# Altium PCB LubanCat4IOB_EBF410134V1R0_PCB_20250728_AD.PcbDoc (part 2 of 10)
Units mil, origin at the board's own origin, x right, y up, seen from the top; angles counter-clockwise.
Board outline 5236.21 x 4055.11 mil, 6 copper layers (TOP, GND02, ART03, PWR04, GND05, BOTTOM), stack 47.2 mil thick; 614 components, 490 nets, 2311 pads, 1916 vias.
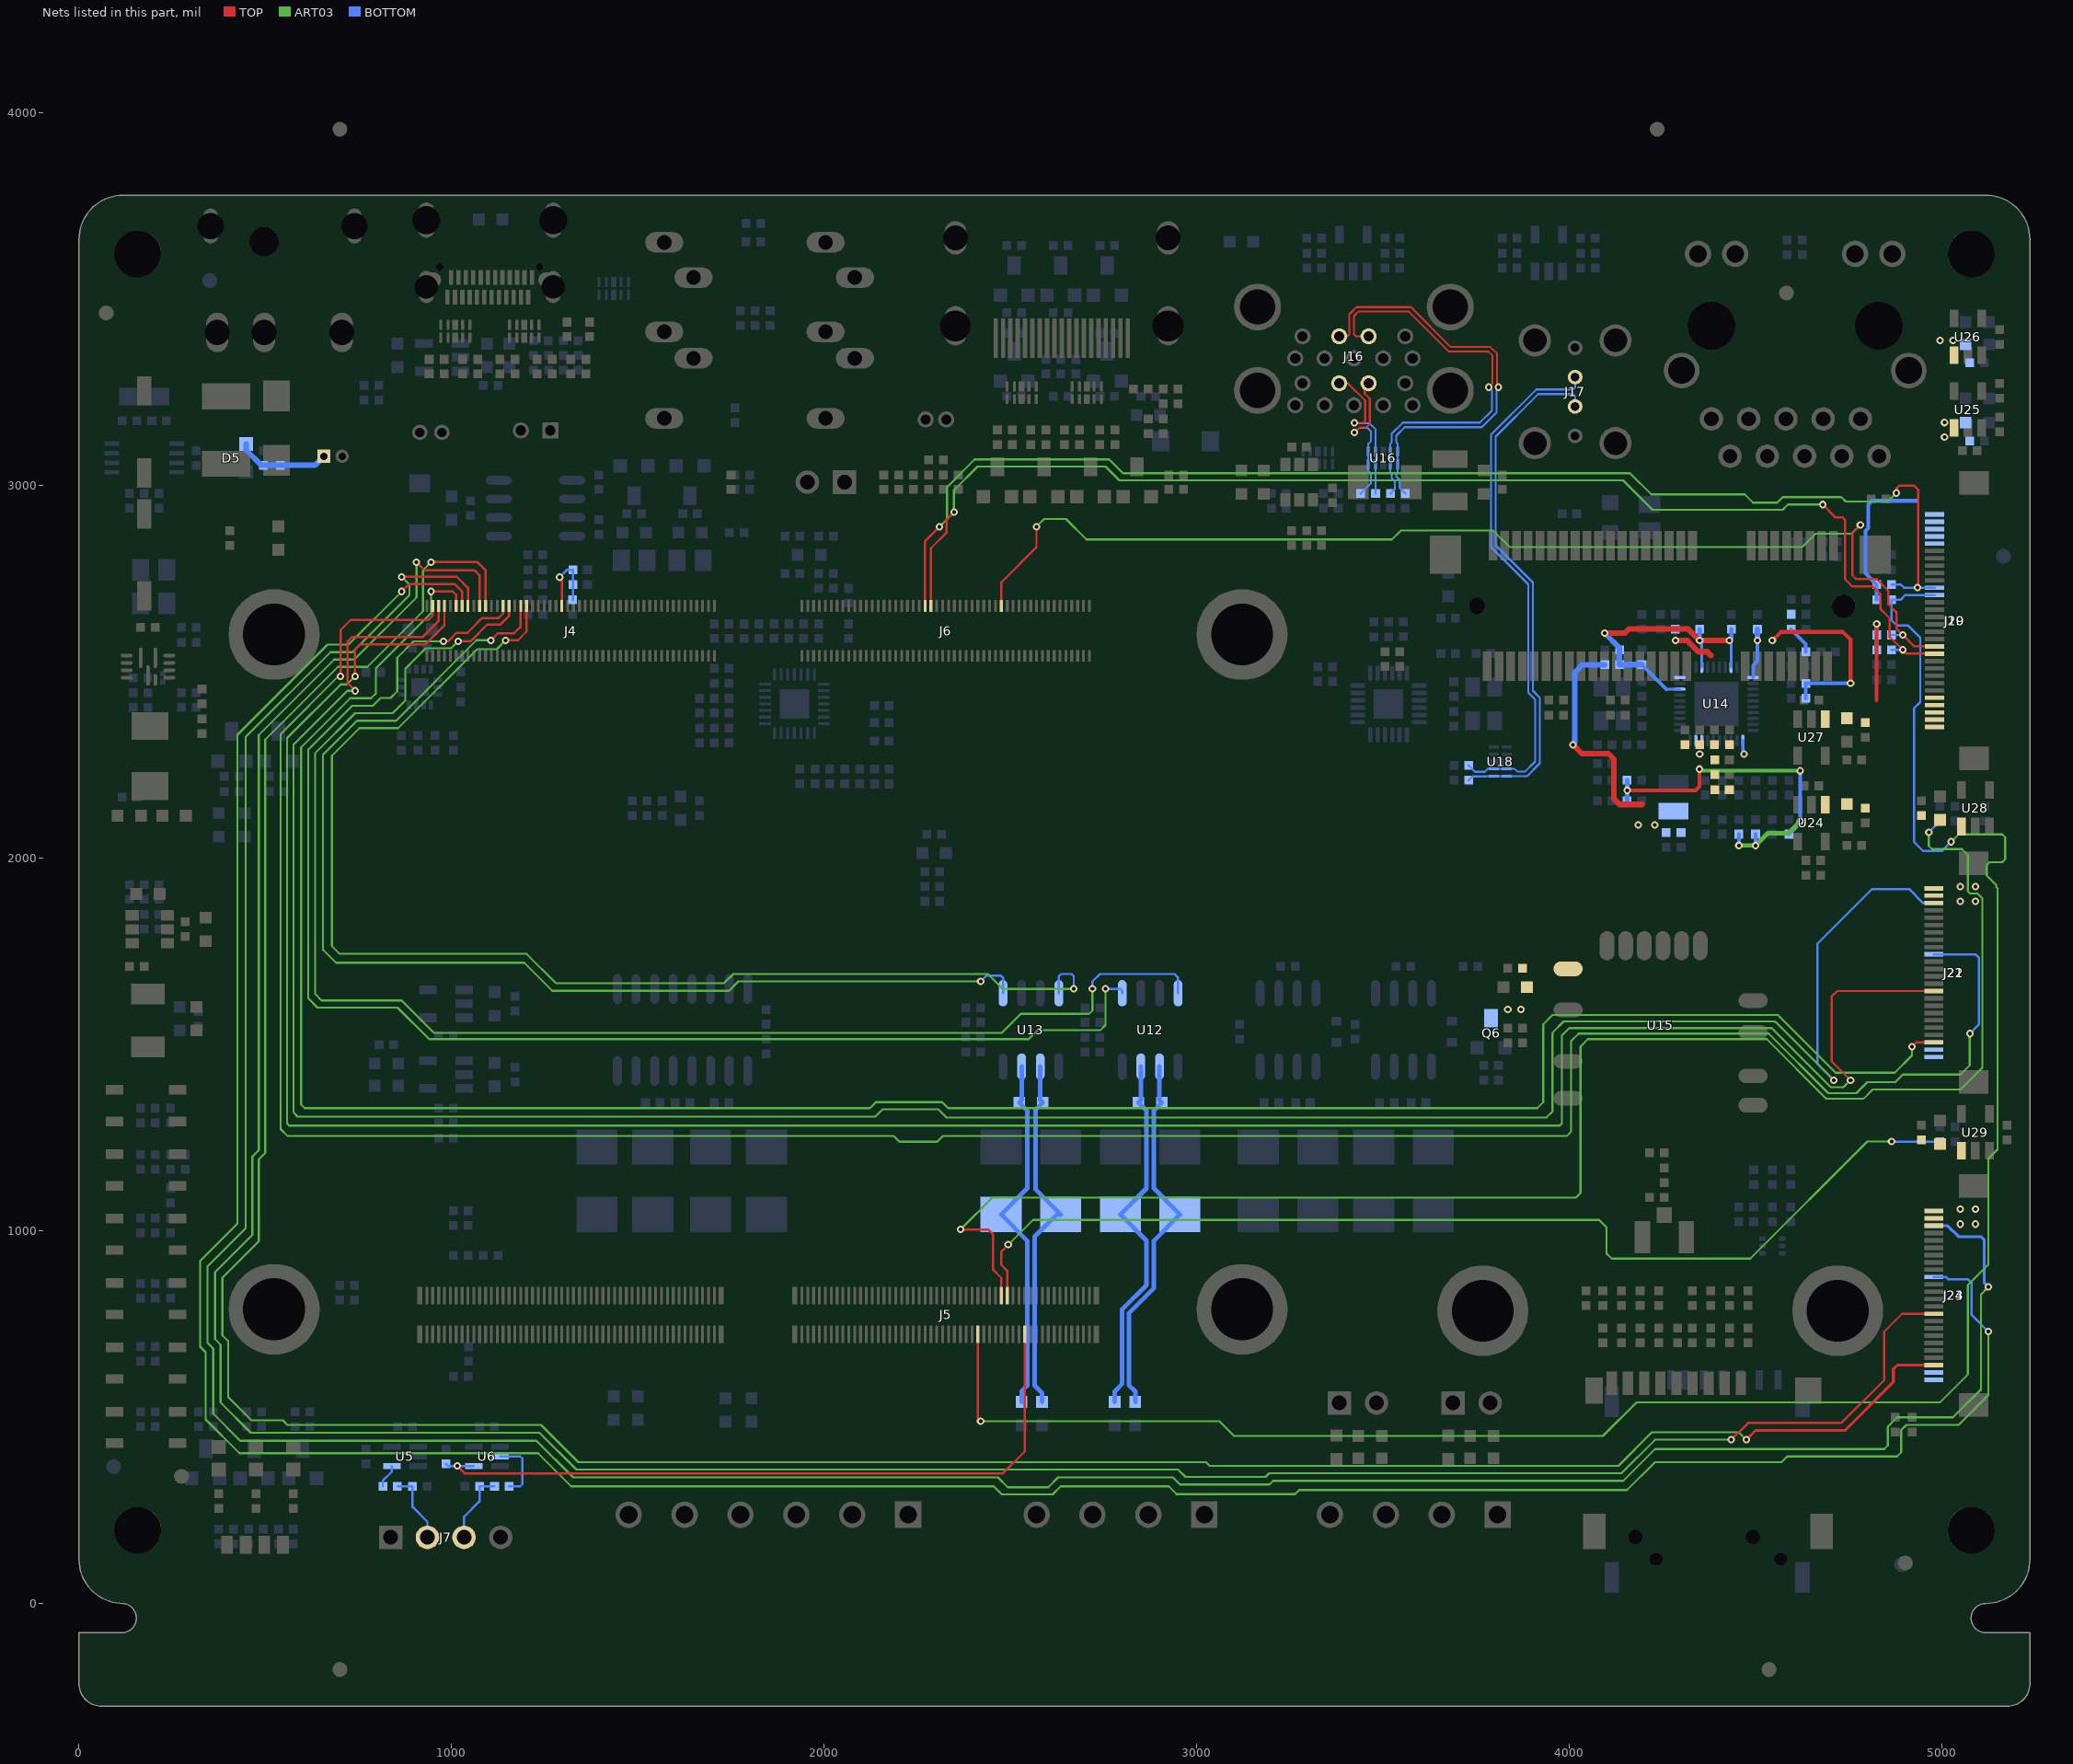
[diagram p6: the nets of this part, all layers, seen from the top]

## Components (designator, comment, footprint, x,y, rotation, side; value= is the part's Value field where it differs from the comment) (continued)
U1 "LPW5209AB5F_SOT23-5_LPW5209AB5F" SOT23-5#1 985,1419.37 r270 bottom
U2 "LPW5209AB5F_SOT23-5_LPW5209AB5F" SOT23-5#1 985,1609.37 r270 bottom
U3 "TP6327GS6_SOT23_6_ASP9135ZC-R" SOT23_6 190,1809.37 r90 top
U4 "MP8759GD-Z_QFN12-2R00X3R00_MP8759GD-Z" QFN12-2R00X3R00 185,2514.37 r270 top
U5 "74LVC1G125_SOT-353_74LVC1G125GW" SOT-353 875,394.37 r270 bottom
U6 "74LVC1G125_SOT-353_74LVC1G125GW" SOT-353 1095,394.37 r270 bottom
U7 "IRM-V838M3-C/TR1_SMD4-6R80X2R50_IRM-V838M3-C/TR1" SMD4-6R80X2R50 472.44,118.11 r180 top
U8 "HYM8563S_MSOP-8_BM8563EMA" MSOP-8 175,3074.37 r90 bottom
U9 "MAX3232CSE_SOIC16_SIT3232EESE" SOIC16 1620,1539.37 r90 bottom
U10 "SIT3088E-8P_SOP8_IC_SIT3088EESA" SOP8 3555,1539.37 r0 bottom
U11 "SIT3088E-8P_SOP8_IC_SIT3088EESA" SOP8 3245,1539.37 r0 bottom
U12 "TJA1057GT3_8P_SOP8_IC_SIT1042AQT/3" SOP8 2875,1539.37 r0 bottom
U13 "TJA1057GT3_8P_SOP8_IC_SIT1042AQT/3" SOP8 2555,1539.37 r0 bottom
U14 "RTL8211F_QFP_40P_R_RTL8211F" QFP_40P_R 4395,2414.37 r270 bottom
U15 "RTL8723_RL-UM02WBS-8723BU_TL8821CUB" RL-UM02WBS-8723BU 4245,1499.37 r180 top
U16 "RCLAMP0524P_SON10_2R50X1R00X0R50_D2550-3R3" SON10_2R50X1R00X0R50 3500,3074.37 r0 bottom
U17 "RCLAMP0524P_SON10_2R50X1R00X0R50_D2550-3R3" SON10_2R50X1R00X0R50 3325,3074.37 r0 bottom
U18 "RCLAMP0524P_SON10_2R50X1R00X0R50_D2550-3R3" SON10_2R50X1R00X0R50 3815,2259.37 r90 bottom
U19 "CH334F_QFN24_CH334F" QFN24 3515,2414.37 r0 bottom
U20 "LPW5209AB5F_SOT23-5_LPW5209AB5F" SOT23-5#2 3420,3624.37 r0 bottom
U21 "LPW5209AB5F_SOT23-5_LPW5209AB5F" SOT23-5#2 3945,3624.37 r0 bottom
U22 "RCLAMP0524P_SON10_2R50X1R00X0R50_D2550-3R3" SON10_2R50X1R00X0R50 2530,3249.37 r180 top
U23 "RCLAMP0524P_SON10_2R50X1R00X0R50_D2550-3R3" SON10_2R50X1R00X0R50 2705,3249.37 r180 top
U24 "LPW5209AB5F_SOT23-5_LPW5209AB5F" SOT23-5#1 4650,2094.37 r180 top
U25 "LPW5209AB5F_SOT23-5_LPW5209AB5F" SOT23-5#1 5070,3204.37 r0 top
U26 "LPW5209AB5F_SOT23-5_LPW5209AB5F" SOT23-5#1 5070,3399.37 r0 top
U27 "LPW5209AB5F_SOT23-5_LPW5209AB5F" SOT23-5#1 4650,2324.37 r180 top
U28 "LPW5209AB5F_SOT23-5_LPW5209AB5F" SOT23-5#1 5090,2134.37 r0 top
U29 "LPW5209AB5F_SOT23-5_LPW5209AB5F" SOT23-5#1 5090,1264.37 r0 top
U30 "TP6327GS6_SOT23_6_ASP9135ZC-R" SOT23_6 3275,3009.37 r180 top
U32 "NUP5120-D_SOT563_NUP5120X6T1G" SOT563 4545,959.37 r90 bottom
U33 "ES8388_QFN28_0R45-4X4EP2R6X2R6_ES8388" QFN28_0R45-4X4EP2R6X2R6 1920,2414.37 r0 bottom
U34 "8002A_SOP8_8002A" SOP8 1225,2939.37 r270 bottom
U35 "RCLAMP0524P_SON10_2R50X1R00X0R50_D2550-3R3" SON10_2R50X1R00X0R50 1195,3414.37 r0 top
U36 "RCLAMP0524P_SON10_2R50X1R00X0R50_D2550-3R3" SON10_2R50X1R00X0R50 1010,3414.37 r0 top
U37 "RCLAMP0524P_SON10_2R50X1R00X0R50_D2550-3R3" SON10_2R50X1R00X0R50 1435,3529.37 r0 bottom
U38 "LPW5209AB5F_SOT23-5_LPW5209AB5F" SOT23-5#1 975,3344.37 r270 bottom
U39 "FUSB302BMPX_WQFN14-0R50-2R5X2R5EP1R45X1R45_FUSB302BMPX" WQFN14-0R50-2R5X2R5EP1R45X1R45 915,2459.37 r0 bottom
Y1 "CRYSTAL_2P_3215_32.768KHZ" 3215 175,3239.37 r0 bottom
Y2 "CRYSTAL_4P_3225_IC_25MHZ" 3225 4115,2414.37 r270 bottom
Y3 "CRYSTAL_4P_3225_IC_12MHZ" 3225 3770,2414.37 r270 bottom
Z1 "DIODE BI-DIR TRIG_ES0402_KLXES15AAA1" ES0402#1 165,494.37 r90 bottom
Z2 "DIODE BI-DIR TRIG_ES0402_KLXES15AAA1" ES0402#1 165,670 r90 bottom
Z3 "DIODE BI-DIR TRIG_ES0402_KLXES15AAA1" ES0402#1 915,314.37 r0 bottom
Z4 "DIODE BI-DIR TRIG_ES0402_KLXES15AAA1" ES0402#2 1055,314.37 r0 bottom
Z5 "DIODE BI-DIR TRIG_ES0402_KLXES15AAA1" ES0402#1 165,839.37 r90 bottom
Z6 "DIODE BI-DIR TRIG_ES0402_KLXES15AAA1" ES0402#1 165,1014.37 r90 bottom
Z7 "DIODE BI-DIR TRIG_ES0402_KLXES15AAA1" ES0402#1 165,1185 r90 bottom
Z8 "DIODE BI-DIR TRIG_ES0402_KLXES15AAA1" ES0402#2 2005,2864.37 r0 bottom
Z9 "DIODE BI-DIR TRIG_ES0402_KLXES15AAA1" ES0402#1 1775,3449.37 r270 bottom
Z10 "DIODE BI-DIR TRIG_ES0402_KLXES15AAA1" ES0402#1 1760,3189.37 r90 bottom
Z11 "DIODE BI-DIR TRIG_ES0402_KLXES15AAA1" ES0402#1 1915,2864.37 r0 bottom
Z12 "DIODE BI-DIR TRIG_ES0402_KLXES15AAA1" ES0402#1 165,1310 r270 bottom

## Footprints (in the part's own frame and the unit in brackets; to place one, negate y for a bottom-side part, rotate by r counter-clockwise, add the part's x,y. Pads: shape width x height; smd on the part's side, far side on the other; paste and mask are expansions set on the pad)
3215 [mil] "3215"
  rect 55.12x47.24 smd: 1(39.4,0) 2(-39.4,0)
  silkscreen extent -75,-35 75,35, body extent -67,-24 67,24, height 150
3225 [mm] "3225"
  rect 1.3x1 smd: 1(-1.15,-0.75) 2(1.15,-0.75) 3(1.15,0.75) 4(-1.15,0.75)
  silkscreen extent -2.41,-1.52 0.3,1.2, body extent -1.9,-1.4 1.9,1.4, height 3.81
C0201 [mm] "C0201"
  rect 0.35x0.35 smd: 1(-0.275,0) 2(0.275,0)
  silkscreen extent -0.51,-0.25 0.51,0.25
C0402#1 [mil] "C0402"
  rect 23.6x23.6 smd: 1(-19.68,0) 2(19.68,0)
  silkscreen extent -37,-17 37,17, body extent -37,-17 37,17, height 150
C0402#2 [mil] "C0402"
  rect 23.6x23.6 smd: 1(19.68,0) 2(-19.68,0)
  silkscreen extent -37,-17 37,17, body extent -37,-17 37,17, height 150
C0603#1 [mil] "C0603"
  rect 31.5x31.5 smd: 1(-31.5,0) 2(31.5,0)
  silkscreen extent -55,-25 55,25, body extent -48,-16 48,16, height 150
C0603#2 [mil] "C0603"
  rect 31.5x31.5 smd: 1(31.5,0) 2(-31.5,0)
  silkscreen extent -55,-25 55,25, body extent -48,-16 48,16, height 150
C0805#1 [mm] "C0805"
  rect 1.16x1.47 smd: 1(0.89,0) 2(-0.89,0)
  silkscreen extent -1.77,-1.04 1.77,1.04, body extent -1.47,-0.74 1.47,0.74, height 3.81
C0805#2 [mm] "C0805"
  rect 1.16x1.47 smd: 1(-0.89,0) 2(0.89,0)
  silkscreen extent -1.77,-1.04 1.77,1.04, body extent -1.47,-0.74 1.47,0.74, height 3.81
CASE-B_3528 [mm] "CASE-B_3528"
  rect 1.2x2.4 smd: 1(-1.45,0) 2(1.45,0)
  silkscreen extent -2.5,-1.4 2.2,1.4, body extent -2.1,-1.2 2.1,1.2, height 3.81
CON_RA_HDMI_19P_0P5_SM [mil] "CON_RA_HDMI_19P_0P5_SM"
  rect 12x106 smd: 1(177.17,201.35) 2(157.48,201.35) 3(137.8,201.35) 4(118.11,201.35) 5(98.43,201.35) 6(78.74,201.35) 7(59.06,201.35) 8(39.37,201.35) 9(19.69,201.35) 10(0,201.35) 11(-19.69,201.35) 12(-39.37,201.35) 13(-59.06,201.35) 14(-78.74,201.35) 15(-98.43,201.35) 16(-118.11,201.35) 17(-137.8,201.35) 18(-157.48,201.35) 19(-177.17,201.35)
  oval 59x106 / inner round 60 / far side oval 59x106 hole 83 slot 35 at 0 deg: G1(285.43,167.89) G2(-285.43,167.89)
  oval 59x90 / inner round 60 / far side oval 59x90 hole 66 slot 35 at 0 deg: G3(285.43,-68.33) G4(-285.43,-68.33)
  silkscreen extent -335,-471 335,241, body extent -315,-254 315,254, height 150
DB2ERC-3P81-4P [mm] "DB2ERC-3P81-4P"
  rect 1.8x1.8 / inner round 1.524 / far side rect 1.8x1.8 hole 1.2: 1(-5.725,-3.5)
  round 1.8 / inner round 1.524 / far side round 1.8 hole 1.2: 2(-1.915,-3.5) 3(1.895,-3.5) 4(5.705,-3.5)
  silkscreen extent -9.21,-4.6 8.11,4.55, body extent -8.2,-4.7 8.2,4.7, height 3.81
DB2ERC-3P81-6P [mm] "DB2ERC-3P81-6P"
  rect 1.8x1.8 / inner round 1.524 / far side rect 1.8x1.8 hole 1.2: 1(-9.525,-3.5)
  round 1.8 hole 1.2: 2(-5.715,-3.5) 5(5.715,-3.5)
  round 1.8 / inner round 1.524 / far side round 1.8 hole 1.2: 3(-1.905,-3.5) 4(1.905,-3.5) 6(9.525,-3.5)
  silkscreen extent -12.82,-4.6 11.93,4.55, body extent -12,-4.7 12,4.7, height 3.81
DC_IN_TH_3P_10R1X11R6 [mm] "DC_IN_TH_3P_10R1X11R6"
  oval 2.4x1.001 hole 1.801 slot 0.399 at 90 deg: 1(-2.826,-4.951) 5(-2.826,4.849)
  oval 2.7x1.5 hole 1.7 slot 0.5 at 90 deg: 2(4.426,-1.301) 3(4.426,3.998)
  oval 2.7x1.5 / inner round 1.524 / far side oval 2.7x1.5 hole 1.7 slot 0.5 at 90 deg: 4(4.426,-4.501)
  round 1.999 hole 1.999 unplated: ""(-1.774,-1.301)
  silkscreen extent -5.9,-5.1 5.75,5, body extent -6.03,-5.8 6.03,5.8, height 3.81
DF40C-100DP-0P4V [mm] "DF40C-100DP-0P4V"
  rect 0.2x1.2 smd: 1(-9.8,1.325) 2(-9.8,-1.325) 3(-9.4,1.325) 4(-9.4,-1.325) 5(-9,1.325) 6(-9,-1.325) 7(-8.6,1.325) 8(-8.6,-1.325) 9(-8.2,1.325) 10(-8.2,-1.325) 11(-7.8,1.325) 12(-7.8,-1.325) 13(-7.4,1.325) 14(-7.4,-1.325) 15(-7,1.325) 16(-7,-1.325) 17(-6.6,1.325) 18(-6.6,-1.325) 19(-6.2,1.325) 20(-6.2,-1.325) 21(-5.8,1.325) 22(-5.8,-1.325) 23(-5.4,1.325) 24(-5.4,-1.325) 25(-5,1.325) 26(-5,-1.325) 27(-4.6,1.325) 28(-4.6,-1.325) 29(-4.2,1.325) 30(-4.2,-1.325) 31(-3.8,1.325) 32(-3.8,-1.325) 33(-3.4,1.325) 34(-3.4,-1.325) 35(-3,1.325) 36(-3,-1.325) 37(-2.6,1.325) 38(-2.6,-1.325) 39(-2.2,1.325) 40(-2.2,-1.325) 41(-1.8,1.325) 42(-1.8,-1.325) 43(-1.4,1.325) 44(-1.4,-1.325) 45(-1,1.325) 46(-1,-1.325) 47(-0.6,1.325) 48(-0.6,-1.325) 49(-0.2,1.325) 50(-0.2,-1.325) 51(0.2,1.325) 52(0.2,-1.325) 53(0.6,1.325) 54(0.6,-1.325) 55(1,1.325) 56(1,-1.325) 57(1.4,1.325) 58(1.4,-1.325) 59(1.8,1.325) 60(1.8,-1.325) 61(2.2,1.325) 62(2.2,-1.325) 63(2.6,1.325) 64(2.6,-1.325) 65(3,1.325) 66(3,-1.325) 67(3.4,1.325) 68(3.4,-1.325) 69(3.8,1.325) 70(3.8,-1.325) 71(4.2,1.325) 72(4.2,-1.325) 73(4.6,1.325) 74(4.6,-1.325) 75(5,1.325) 76(5,-1.325) 77(5.4,1.325) 78(5.4,-1.325) 79(5.8,1.325) 80(5.8,-1.325) 81(6.2,1.325) 82(6.2,-1.325) 83(6.6,1.325) 84(6.6,-1.325) 85(7,1.325) 86(7,-1.325) 87(7.4,1.325) 88(7.4,-1.325) 89(7.8,1.325) 90(7.8,-1.325) 91(8.2,1.325) 92(8.2,-1.325) 93(8.6,1.325) 94(8.6,-1.325) 95(9,1.325) 96(9,-1.325) 97(9.4,1.325) 98(9.4,-1.325) 99(9.8,1.325) 100(9.8,-1.325)
  rect 0.35x1.2 smd: 101(-10.275,1.325) 102(-10.275,-1.325) 103(10.275,1.325) 104(10.275,-1.325)
  silkscreen extent -10.8,-0.92 10.8,2.4, body extent -10.9,-2 10.9,2, height 3.81
DF40HC-100DS-0P4V [mm] "DF40HC-100DS-0P4V"
  rect 0.2x0.8 smd: 1(-9.8,-1.7) 2(-9.8,1.7) 3(-9.4,-1.7) 4(-9.4,1.7) 5(-9,-1.7) 6(-9,1.7) 7(-8.6,-1.7) 8(-8.6,1.7) 9(-8.2,-1.7) 10(-8.2,1.7) 11(-7.8,-1.7) 12(-7.8,1.7) 13(-7.4,-1.7) 14(-7.4,1.7) 15(-7,-1.7) 16(-7,1.7) 17(-6.6,-1.7) 18(-6.6,1.7) 19(-6.2,-1.7) 20(-6.2,1.7) 21(-5.8,-1.7) 22(-5.8,1.7) 23(-5.4,-1.7) 24(-5.4,1.7) 25(-5,-1.7) 26(-5,1.7) 27(-4.6,-1.7) 28(-4.6,1.7) 29(-4.2,-1.7) 30(-4.2,1.7) 31(-3.8,-1.7) 32(-3.8,1.7) 33(-3.4,-1.7) 34(-3.4,1.7) 35(-3,-1.7) 36(-3,1.7) 37(-2.6,-1.7) 38(-2.6,1.7) 39(-2.2,-1.7) 40(-2.2,1.7) 41(-1.8,-1.7) 42(-1.8,1.7) 43(-1.4,-1.7) 44(-1.4,1.7) 45(-1,-1.7) 46(-1,1.7) 47(-0.6,-1.7) 48(-0.6,1.7) 49(-0.2,-1.7) 50(-0.2,1.7) 51(0.2,-1.7) 52(0.2,1.7) 53(0.6,-1.7) 54(0.6,1.7) 55(1,-1.7) 56(1,1.7) 57(1.4,-1.7) 58(1.4,1.7) 59(1.8,-1.7) 60(1.8,1.7) 61(2.2,-1.7) 62(2.2,1.7) 63(2.6,-1.7) 64(2.6,1.7) 65(3,-1.7) 66(3,1.7) 67(3.4,-1.7) 68(3.4,1.7) 69(3.8,-1.7) 70(3.8,1.7) 71(4.2,-1.7) 72(4.2,1.7) 73(4.6,-1.7) 74(4.6,1.7) 75(5,-1.7) 76(5,1.7) 77(5.4,-1.7) 78(5.4,1.7) 79(5.8,-1.7) 80(5.8,1.7) 81(6.2,-1.7) 82(6.2,1.7) 83(6.6,-1.7) 84(6.6,1.7) 85(7,-1.7) 86(7,1.7) 87(7.4,-1.7) 88(7.4,1.7) 89(7.8,-1.7) 90(7.8,1.7) 91(8.2,-1.7) 92(8.2,1.7) 93(8.6,-1.7) 94(8.6,1.7) 95(9,-1.7) 96(9,1.7) 97(9.4,-1.7) 98(9.4,1.7) 99(9.8,-1.7) 100(9.8,1.7)
  silkscreen extent -11.3,-2.55 11.3,1.5, body extent -11.4,-2.2 11.4,2.2, height 3.81
EAR_JACK [mm] "EAR_JACK"
  oval 1.4x2.6 / inner round 1.524 / far side oval 1.4x2.6 hole 1 slot 2 at 90 deg: 1(-5.904,-0.05) 2(-3.504,1.95) 3(1.996,1.95) 4(6.096,-0.05) 5(0.196,-0.05)
  silkscreen extent -11.12,-4.06 7.2,4.06, body extent -7.2,-4.15 7.2,4.15, height 3.81
EC6P3 [mil] "EC6P3"
  rect 39.4x78.7 smd: 1(0,110.24) 2(0,-110.24)
  silkscreen extent -130,-130 130,130, body extent -138,-157 138,157, height 150
ES0402#1 [mil] "ES0402"
  rect 23.6x23.6 smd: 1(-19.68,0) 2(19.68,0)
  silkscreen extent -37,-17 37,17, body extent -37,-17 37,17, height 150
ES0402#2 [mil] "ES0402"
  rect 23.6x23.6 smd: 1(19.68,0) 2(-19.68,0)
  silkscreen extent -37,-17 37,17, body extent -37,-17 37,17, height 150
F1812 [mm] "F1812"
  rect 1.78x3.3 smd: 1(-2.305,0) 2(2.305,0)
  silkscreen extent -3.4,-1.9 3.4,1.9, body extent -3.4,-1.9 3.4,1.9, height 3.81
FPC-30P-0P5 [mm] "FPC-30P-0P5"
  rect 0.3x1.3 smd: 1(-7.25,2.733) 2(-6.75,2.733) 3(-6.25,2.733) 4(-5.75,2.733) 5(-5.25,2.733) 6(-4.75,2.733) 7(-4.25,2.733) 8(-3.75,2.733) 9(-3.25,2.733) 10(-2.75,2.733) 11(-2.25,2.733) 12(-1.75,2.733) 13(-1.25,2.733) 14(-0.75,2.733) 15(-0.25,2.733) 16(0.25,2.733) 17(0.75,2.733) 18(1.25,2.733) 19(1.75,2.733) 20(2.25,2.733) 21(2.75,2.733) 22(3.25,2.733) 23(3.75,2.733) 24(4.25,2.733) 25(4.75,2.733) 26(5.25,2.733) 27(5.75,2.733) 28(6.25,2.733) 29(6.75,2.733) 30(7.25,2.733)
  rect 1.6x2 smd: 31(9.4,0.032) 32(-9.4,0.032)
  silkscreen extent -10.05,-3.27 10.05,4.14, body extent -10.05,-3.35 10.05,3.35, height 3.81
FPC_24P_0P5 [mm] "FPC_24P_0P5"
  rect 0.3x1.3 smd: 1(-5.75,-2.701) 2(-5.25,-2.701) 3(-4.75,-2.701) 4(-4.25,-2.701) 5(-3.75,-2.701) 6(-3.25,-2.701) 7(-2.75,-2.701) 8(-2.25,-2.701) 9(-1.75,-2.701) 10(-1.25,-2.701) 11(-0.75,-2.701) 12(-0.25,-2.701) 13(0.25,-2.701) 14(0.75,-2.701) 15(1.25,-2.701) 16(1.75,-2.701) 17(2.25,-2.701) 18(2.75,-2.701) 19(3.25,-2.701) 20(3.75,-2.701) 21(4.25,-2.701) 22(4.75,-2.701) 23(5.25,-2.701) 24(5.75,-2.701)
  rect 1.6x2 smd: 25(7.45,0.001) 26(-7.45,0.001)
  silkscreen extent -8.1,-3.95 8.1,3.35
GH1P25_TH_2P [mm] "GH1P25_TH_2P"
  rect 0.9x0.9 / inner round 1.524 / far side rect 0.9x0.9 hole 0.5: 1(-0.626,-0.849)
  round 0.9 hole 0.5: 2(0.624,-0.849)
  silkscreen extent -2.2,-1.75 2.2,1.75
HDR1X2-2R54-TM-VM [mm] "HDR1X2-2R54-TM-VM"
  rect 1.6x1.6 / inner round 1.524 / far side rect 1.6x1.6 hole 1: 1(-1.27,0)
  round 1.6 / inner round 1.524 / far side round 1.6 hole 1: 2(1.27,0)
  silkscreen extent -2.54,-1.25 2.54,1.25, body extent -2.54,-1.25 2.54,1.25, height 3.81
HY911130A [mm] "HY911130A"
  round 1.6 / inner round 1.524 / far side round 1.6 hole 1: 1(5.72,-8.79) 2(4.45,-6.25) 3(3.18,-8.79) 4(1.91,-6.25) 5(0.64,-8.79) 6(-0.63,-6.25) 7(-1.9,-8.79) 8(-3.17,-6.25) 9(-4.44,-8.79)
  round 1.6 hole 1: 10(-5.71,-6.25)
  round 1.8 / inner round 1.524 / far side round 1.8 hole 1.2: 11(6.625,5) 12(4.085,5) 13(-4.085,5) 14(-6.625,5)
  round 2.43 / inner round 1.524 / far side round 2.43 hole 1.83: 15(7.745,-2.95) 16(-7.745,-2.95)
  round 3.25 hole 3.25 unplated: ""(-5.715,0.1) ""(5.715,0.1)
  silkscreen extent -8.02,-10.3 8.02,17.1, body extent -9.2,-11.1 9.2,11.1, height 3.81
L0518 [mm] "L0518"
  rect 1.9x2.5 smd: 1(-2.05,0) 2(2.05,0)
  silkscreen extent -2.75,-2.65 2.75,2.65, body extent -3.1,-2.8 3.1,2.8, height 3.81
L0603#1 [mil] "L0603"
  rect 31.5x31.5 smd: 1(-31.5,0) 2(31.5,0)
  silkscreen extent -54,-24 55,24, body extent -47,-16 47,16, height 150
L0603#2 [mil] "L0603"
  rect 31.5x31.5 smd: 1(31.5,0) 2(-31.5,0)
  silkscreen extent -55,-24 54,24, body extent -47,-16 47,16, height 150
L2520 [mil] "L2520"
  rect 44x80 smd: 1(-37.75,0) 2(37.75,0)
  silkscreen extent -68,-48 68,48, body extent -65,-45 65,45, height 150
L4520 [mil] "L4520"
  rect 55.12x90.55 smd: 1(-70.97,-0.1) 2(70.77,-0.1)
  silkscreen extent -91,-87 90,87, body extent -91,-87 91,87, height 150
LED0603 [mil] "LED0603"
  rect 36.61x38.58 smd: 1(30.32,0) 2(-30.31,0)
  silkscreen extent -60,-31 80,31, body extent -49,-19 49,19, height 150
MIC2-4R00-TM [mm] "MIC2-4R00-TM"
  round 1.1 / inner round 1.524 / far side round 1.1 hole 0.7: 1(-0.7,-0.55) 2(0.7,-0.55)
  silkscreen extent -2,-2 2,2, body extent -2.11,-2.11 2.11,2.11, height 3.81
MSOP-8 [mm] "MSOP-8"
  rect 0.3x1 smd: 1(-0.975,-2.2) 2(-0.325,-2.2) 3(0.325,-2.2) 4(0.975,-2.2) 5(0.975,2.2) 6(0.325,2.2) 7(-0.325,2.2) 8(-0.975,2.2)
  silkscreen extent -1.5,-3.3 1.5,1.5, body extent -1.5,-2.8 1.5,2.8, height 3.81
NANO_SIM [mm] "NANO_SIM"
  rect 0.5x1.3 smd: 1(-0.25,-6.94) 2(2.29,-6.94) 3(4.83,-6.94) 4(-2.47,-6.94) 5(-1.52,-6.94) 6(1.02,-6.94) 7(3.56,-6.94)
  rect 1x2.1 smd: 8(6.5,-5.46) 9(-6.5,-5.46) 10(6.5,6.54) 11(-6.5,6.54)
  round 0.9 hole 0.9 unplated: ""(-3.5,5.29) ""(5,5.29)
  silkscreen extent -6.14,-5.9 6.14,7.6, body extent -7.05,-7.64 7.05,7.64, height 3.81
NPTH_M3 [mm] "NPTH_M3"
  round 3.2 / inner round 1.524 / far side round 3.2 hole 3.2 unplated: 1(0,0)
  body extent -3.11,-3.11 3.11,3.11, height 3.81
PCIE_52P [mm] "PCIE_52P"
  rect 0.6x2 smd: 1(-11.8,-4.1) 2(-11.4,4.1) 3(-11,-4.1) 4(-10.6,4.1) 5(-10.2,-4.1) 6(-9.8,4.1) 7(-9.4,-4.1) 8(-9,4.1) 9(-8.6,-4.1) 10(-8.2,4.1) 11(-7.8,-4.1) 12(-7.4,4.1) 13(-7,-4.1) 14(-6.6,4.1) 15(-6.2,-4.1) 16(-5.8,4.1) 17(-2.2,-4.1) 18(-1.8,4.1) 19(-1.4,-4.1) 20(-1,4.1) 21(-0.6,-4.1) 22(-0.2,4.1) 23(0.2,-4.1) 24(0.6,4.1) 25(1,-4.1) 26(1.4,4.1) 27(1.8,-4.1) 28(2.2,4.1) 29(2.6,-4.1) 30(3,4.1) 31(3.4,-4.1) 32(3.8,4.1) 33(4.2,-4.1) 34(4.6,4.1) 35(5,-4.1) 36(5.4,4.1) 37(5.8,-4.1) 38(6.2,4.1) 39(6.6,-4.1) 40(7,4.1) 41(7.4,-4.1) 42(7.8,4.1) 43(8.2,-4.1) 44(8.6,4.1) 45(9,-4.1) 46(9.4,4.1) 47(9.8,-4.1) 48(10.2,4.1) 49(10.6,-4.1) 50(11,4.1) 51(11.4,-4.1) 52(11.8,4.1)
  rect 2.15x2.6 smd: 53(14.65,-3.5) 54(-14.65,-3.5)
  round 1.6 hole 1.6 unplated: ""(-12.5,0)
  round 1.1 hole 1.1 unplated: ""(12.5,0)
  silkscreen extent -15,-4.6 15,50.95, body extent -15.8,-5.2 15.8,5.2, height 3.81
PH-1X2-2P0_L [mm] "PH-1X2-2P0_L"
  rect 1.1x1.1 / inner round 1.524 / far side rect 1.1x1.1 hole 0.7: 1(-1,-0.6)
  round 1.1 / inner round 1.524 / far side round 1.1 hole 0.7: 2(1,-0.6)
  silkscreen extent -3,-2.6 3,2.6, body extent -3.1,-2.7 3.1,2.7, height 3.81
QFN12-2R00X3R00 [mm] "QFN12-2R00X3R00"
  oval 1.4x0.25 smd: 1(-0.6,0.5) 2(-0.6,-0.5) 7(0.6,0)
  oval 0.25x0.8 smd: 3(-0.75,-1.45) 4(-0.25,-1.45) 5(0.25,-1.45) 6(0.75,-1.45) 9(0.75,1.45) 10(0.25,1.45) 11(-0.25,1.45) 12(-0.75,1.45)
  oval 0.8x0.25 smd: 8(0.9,0.5)
  silkscreen extent -2.29,-2 1.5,2, body extent -1.5,-2 1.5,2, height 3.81
QFN24 [mm] "QFN24"
  rect 1x0.3 smd: 1(2.1,-1.25) 2(2.1,-0.75) 3(2.1,-0.25) 4(2.1,0.25) 5(2.1,0.75) 6(2.1,1.25) 13(-2.1,1.25) 14(-2.1,0.75) 15(-2.1,0.25) 16(-2.1,-0.25) 17(-2.1,-0.75) 18(-2.1,-1.25)
  rect 0.3x1 smd: 7(1.25,2.1) 8(0.75,2.1) 9(0.25,2.1) 10(-0.25,2.1) 11(-0.75,2.1) 12(-1.25,2.1) 19(-1.25,-2.1) 20(-0.75,-2.1) 21(-0.25,-2.1) 22(0.25,-2.1) 23(0.75,-2.1) 24(1.25,-2.1)
  rect 2x2 smd: 25(0,0)
  silkscreen extent -2.1,-2.29 2.79,2.1, body extent -2.7,-2.7 2.7,2.7, height 3.81
QFN28_0R45-4X4EP2R6X2R6 [mm] "QFN28_0R45-4X4EP2R6X2R6"
  oval 0.8x0.2 smd: 1(2,-1.35)
  rect 0.8x0.2 smd: 2(2,-0.9) 3(2,-0.45) 4(2,0) 5(2,0.45) 6(2,0.9) 7(2,1.35) 15(-2,1.35) 16(-2,0.9) 17(-2,0.45) 18(-2,0) 19(-2,-0.45) 20(-2,-0.9) 21(-2,-1.35)
  rect 0.2x0.8 smd: 8(1.35,2) 9(0.9,2) 10(0.45,2) 11(0,2) 12(-0.45,2) 13(-0.9,2) 14(-1.35,2) 22(-1.35,-2) 23(-0.9,-2) 24(-0.45,-2) 25(0,-2) 26(0.45,-2) 27(0.9,-2) 28(1.35,-2)
  rect 2x2 smd: 29(0,0)
  silkscreen extent -2,-2.03 3.15,2, body extent -2.5,-2.5 2.5,2.5, height 3.81
QFP_40P_R [mil] "QFP_40P_R"
  oval 31.5x8.66 smd: 1(-98.43,70.87) 2(-98.43,55.12) 3(-98.43,39.37) 4(-98.43,23.62) 5(-98.43,7.87) 6(-98.43,-7.87) 7(-98.43,-23.62) 8(-98.43,-39.37) 9(-98.43,-55.12) 10(-98.43,-70.87) 21(98.43,-70.87) 22(98.43,-55.12) 23(98.43,-39.37) 24(98.43,-23.62) 25(98.43,-7.87) 26(98.43,7.87) 27(98.43,23.62) 28(98.43,39.37) 29(98.43,55.12) 30(98.43,70.87)
  oval 8.66x31.5 smd: 11(-70.87,-98.43) 12(-55.12,-98.43) 13(-39.37,-98.43) 14(-23.62,-98.43) 15(-7.87,-98.43) 16(7.87,-98.43) 17(23.62,-98.43) 18(39.37,-98.43) 19(55.12,-98.43) 20(70.87,-98.43) 31(70.87,98.43) 32(55.12,98.43) 33(39.37,98.43) 34(23.62,98.43) 35(7.87,98.43) 36(-7.87,98.43) 37(-23.62,98.43) 38(-39.37,98.43) 39(-55.12,98.43) 40(-70.87,98.43)
  rect 118.11x118.11 smd: 41(0,0)
  silkscreen extent -124,-98 98,124, body extent -116,-116 116,116, height 150
R0402#1 [mil] "R0402"
  rect 23.6x23.6 smd: 1(19.68,0) 2(-19.68,0)
  silkscreen extent -37,-17 37,17, body extent -37,-17 37,17, height 150
R0402#2 [mil] "R0402"
  rect 23.6x23.6 smd: 1(-19.68,0) 2(19.68,0)
  silkscreen extent -37,-17 37,17, body extent -37,-17 37,17, height 150
R0603#1 [mil] "R0603"
  rect 31.5x31.5 smd: 1(-31.5,0) 2(31.5,0)
  silkscreen extent -54,-24 55,24, body extent -47,-16 47,16, height 150
R0603#2 [mil] "R0603"
  rect 31.5x31.5 smd: 1(31.5,0) 2(-31.5,0)
  silkscreen extent -55,-24 54,24, body extent -47,-16 47,16, height 150
R0805 [mil] "R0805"
  rect 40x45 smd: 1(-40,0) 2(40,0)
  silkscreen extent -70,-35 70,35, body extent -60,-25 60,25, height 150
RL-UM02WBS-8723BU [mm] "RL-UM02WBS-8723BU"
  oval 2x1 smd: 1(-6.3,4.122) 2(-6.3,2.122) 3(-6.3,-0.858) 4(-6.3,-3.018) 5(6.3,3.652) 6(6.3,1.122) 7(6.3,-2.378) 8(6.3,-5.178)
  oval 1x2 smd: 9(3.65,-6.748) 10(2.38,-6.748) 11(1.11,-6.748) 12(-0.16,-6.748) 13(-1.43,-6.748) 14(-2.7,-6.748)
  silkscreen extent -6.1,-6.55 6.1,6.45, body extent -6.1,-6.45 6.1,6.45, height 3.81
SMA_CA [mm] "SMA_CA"
  rect 2.1x1.8 smd: 1(-2.2,0) 2(2.2,0)
  silkscreen extent -2.2,-1.3 2.2,1.3, body extent -3.3,-1.4 3.3,1.4, height 3.81
SMB-CA [mm] "SMB-CA"
  rect 2.4x2.8 smd: 1(-2.3,0) 2(2.3,0)
  silkscreen extent -2.3,-1.8 2.3,1.8, body extent -3.5,-1.8 3.5,1.8, height 3.81
SMD4-6R80X2R50 [mm] "SMD4-6R80X2R50"
  rect 0.8x1.2 smd: 1(1.905,-1) 2(0.635,-1) 3(-0.635,-1) 4(-1.905,-1)
  silkscreen extent -3.4,-2.45 3.4,1.71, body extent -3.6,-1.8 3.6,1.8, height 3.81
SMTSO-M2R5 [mm] "SMTSO-M2R5"
  round 6.2 / inner round 5.2 / far side round 5.2 hole 4.22: 1(0,0)
  body extent -3.21,-3.21 3.21,3.21, height 3.81
SOD523 [mm] "SOD523"
  rect 0.6x0.7 smd: 1(-0.71,0) 2(0.71,0)
  silkscreen extent -1.3,-0.5 0.6,0.5, body extent -1.1,-0.4 1.1,0.4, height 3.81
SOD-123#1 [mm] "SOD-123"
  rect 1.2x1.4 smd: 1(1.7,0) 2(-1.7,0)
  silkscreen extent -1.8,-0.9 1.8,0.9, body extent -2.4,-1 2.4,1, height 3.81
SOD-123#2 [mm] "SOD-123"
  rect 1.2x1.4 smd: 1(-1.7,0) 2(1.7,0)
  silkscreen extent -1.8,-0.9 1.8,0.9, body extent -2.4,-1 2.4,1, height 3.81
SOIC16 [mil] "SOIC16"
  oval 80x24 smd: 1(-109.8,174.8) 2(-109.8,125.2) 3(-109.8,74.8) 4(-109.8,25.2) 5(-109.8,-25.2) 6(-109.8,-74.8) 7(-109.8,-125.2) 8(-109.8,-174.8) 9(109.8,-174.8) 10(109.8,-125.2) 11(109.8,-74.8) 12(109.8,-25.2) 13(109.8,25.2) 14(109.8,74.8) 15(109.8,125.2) 16(109.8,174.8)
  silkscreen extent -135,-197 59,225, body extent -157,-205 157,205, height 150
SON10_2R50X1R00X0R50 [mm] "SON10_2R50X1R00X0R50"
  rect 0.2x0.68 smd: 1(-1,-0.437) 2(-0.5,-0.437) 4(0.5,-0.437) 5(1,-0.437) 6(1,0.437) 7(0.5,0.437) 9(-0.5,0.437) 10(-1,0.437)
  rect 0.4x0.68 smd: 3(0,-0.437) 8(0,0.437)
  silkscreen extent -2.05,-0.98 1.25,0.5, body extent -1.39,-0.64 1.39,0.64, height 3.81
SOP8 [mm] "SOP8"
  oval 0.6x1.8 smd: 1(-1.905,-2.5) 2(-0.635,-2.5) 3(0.635,-2.5) 4(1.905,-2.5) 5(1.905,2.5) 6(0.635,2.5) 7(-0.635,2.5) 8(-1.905,2.5)
  silkscreen extent -2.5,-4.15 2.5,1.4, body extent -2.5,-3.5 2.5,3.5, height 3.81
SOT23#1 [mil] "SOT23"
  rect 36x36 smd: 1(-37.5,-43.5) 2(37.5,-43.5)
  rect 36x50 smd: 3(0,36.5)
  silkscreen extent -55,-54 55,36, body extent -56,-62 56,62, height 150
SOT23#2 [mil] "SOT23"
  rect 36x36 smd: 1(37.5,43.5) 2(-37.5,43.5)
  rect 36x50 smd: 3(0,-36.5)
  silkscreen extent -55,-36 55,54, body extent -56,-62 56,62, height 150
SOT23-5#1 [mm] "SOT23-5"
  rect 0.599x1.199 smd: 1(-0.95,-1.25) 2(0,-1.25) 3(0.95,-1.25) 4(0.95,1.25) 5(-0.95,1.25)
  silkscreen extent -2.02,-1.92 1.5,0.9, body extent -1.6,-1.9 1.6,1.9, height 3.81
SOT23-5#2 [mm] "SOT23-5"
  rect 0.599x1.199 smd: 1(0.95,1.25) 2(0,1.25) 3(-0.95,1.25) 4(-0.95,-1.25) 5(0.95,-1.25)
  silkscreen extent -1.5,-0.9 1.5,2.55, body extent -1.6,-1.9 1.6,1.9, height 3.81
SOT23_6 [mm] "SOT23_6"
  rect 0.7x0.9 smd: 1(-0.95,-1.2) 2(0,-1.2) 3(0.95,-1.2) 4(0.95,1.2) 5(0,1.2) 6(-0.95,1.2)
  silkscreen extent -2.19,-1.25 1.4,0.6, body extent -1.4,-1.2 1.4,1.2, height 3.81
SOT563 [mm] "SOT563"
  rect 0.3x0.45 smd: 1(-0.5,-0.675) 2(0,-0.675) 3(0.5,-0.675) 4(0.5,0.675) 5(0,0.675) 6(-0.5,0.675)
  silkscreen extent -0.9,-1.8 0.9,1.1, body extent -0.9,-1.1 0.9,1.1, height 3.81
SOT-353 [mil] "SOT-353"
  rect 16x47 smd: 1(-25.91,-35.43) 2(-0.32,-35.43) 3(25.28,-35.43) 4(25.28,35.43) 5(-25.91,35.43)
  silkscreen extent -55,-80 45,70, body extent -40,-65 40,65, height 150
SW4-4R20X3R25-SM [mm] "SW4-4R20X3R25-SM"
  rect 1.2x0.65 smd: 1(-2.15,1.075) 2(2.15,1.075) 3(2.15,-1.075) 4(-2.15,-1.075)
  silkscreen extent -2.1,-1.6 2.1,1.6, body extent -2.8,-1.7 2.8,1.7, height 3.81
TFCARD [mm] "TFCARD"
  rect 0.7x1.6 smd: 1(2.25,6.85) 2(1.15,6.85) 3(0.05,6.85) 4(-1.05,6.85) 5(-2.15,6.85) 6(-3.25,6.85) 7(-4.35,6.85) 8(-5.45,6.85) 9(-6.55,6.85)
  rect 1.2x1.778 smd: 10(-7.75,6.35)
  rect 1.524x2.413 smd: 11(-7.75,-3.25) 12(7.75,-3.25)
  rect 1.778x1.778 smd: 13(6.85,6.35)
  round 1 hole 1 unplated: ""(-4.95,-3.65) ""(3.05,-3.65)
  silkscreen extent -7.45,-12.85 7.45,6.85, body extent -8.51,-7.65 8.51,7.65, height 3.81
UFL-3 [mil] "UFL-3"
  rect 41.34x41.34 smd: 1(0,-40.85)
  rect 41.34x86.61 smd: 2(-59.06,18.21) 3(59.06,18.21)
  body extent -80,-62 80,62, height 150
USB3D0-AF-18P [mm] "USB3D0-AF-18P"
  round 1.1 / inner round 1.524 / far side round 1.1 hole 0.7: 1(-3.5,2.899) 2(-1.001,2.899) 3(1.001,2.899) 5(4,4.401) 6(1.999,4.401) 8(-1.999,4.401) 9(-4.001,4.401) 10(-3.5,6.1) 11(-1.001,6.1) 12(1.001,6.1) 14(4,7.601) 15(1.999,7.601) 17(-1.999,7.601) 18(-4.001,7.601)
  round 1.1 hole 0.7: 4(3.5,2.899) 7(0,4.401) 13(3.5,6.1) 16(0,7.601)
  round 3.2 hole 2.4: 19(6.571,0.9) 20(6.571,6.58) 21(-6.571,6.58) 22(-6.571,0.9)
  silkscreen extent -8,-16.73 8,8.77, body extent -8.4,-8.8 8.4,8.8, height 3.81
USB-AF [mm] "USB-AF"
  round 1 / inner round 1.524 / far side round 1 hole 0.6: 1(0,-2.498) 2(0,-4.5) 3(0,-6.502)
  round 1 hole 0.6: 4(0,-8.504)
  round 2.2 hole 1.6: 5(2.749,-9) 6(2.749,-2) 7(-2.751,-2) 8(-2.751,-9)
  silkscreen extent -4.5,-9.7 4.5,14.43, body extent -4.1,-10.3 4.1,10.3, height 3.81
USB-C-SMD_TYC-324G [mm] "USB-C-SMD_TYC-324G"
  oval 1x2.2 / inner round 1.524 / far side oval 1x2.2 hole 1.6 slot 0.6 at 0 deg: 1(-4.32,2.99) 4(4.32,2.99)
  oval 1.2x2.4 / inner round 1.524 / far side oval 1.2x2.4 hole 1.9 slot 0.6 at 0 deg: 2(-4.32,-1.56) 3(4.32,-1.56)
  rect 0.3x1 smd: A1(-2.62,3.68) A2(-2.13,3.68) A3(-1.63,3.68) A4(-1.13,3.68) A5(-0.62,3.68) A6(-0.12,3.68) A7(0.38,3.68) A8(0.88,3.68) A9(1.37,3.68) A10(1.87,3.68) A11(2.37,3.68) A12(2.88,3.68) B1(2.63,2.34) B2(2.13,2.34) B3(1.63,2.34) B4(1.13,2.34) B5(0.62,2.34) B6(0.12,2.34) B7(-0.38,2.34) B8(-0.87,2.34) B9(-1.37,2.34) B10(-1.87,2.34) B11(-2.37,2.34) B12(-2.88,2.34)
  oval 1.5x1 hole 0.5 slot 1.2 at 0 deg: ""(-4.06,2.51) ""(4.06,2.51)
  round 0.5 hole 0.5 unplated: ""(-3.4,1.63) ""(3.4,1.63)
  silkscreen extent -6,-10.14 6,1.67, body extent -4.97,-4.24 4.97,4.24, height 3.81
WQFN14-0R50-2R5X2R5EP1R45X1R45 [mm] "WQFN14-0R50-2R5X2R5EP1R45X1R45"
  rect 0.6x0.3 smd: 1(1.21,-0.5) 2(1.21,0) 3(1.21,0.5) 8(-1.21,0.5) 9(-1.21,0) 10(-1.21,-0.5)
  rect 0.3x0.6 smd: 4(0.75,1.21) 5(0.25,1.21) 6(-0.25,1.21) 7(-0.75,1.21) 11(-0.75,-1.21) 12(-0.25,-1.21) 13(0.25,-1.21) 14(0.75,-1.21)
  rect 1.2x1.2 smd: 15(0,0)
  silkscreen extent -1.25,-1.25 2.25,1.25, body extent -1.6,-1.6 1.6,1.6, height 3.81
XH2R54-4P-V [mm] "XH2R54-4P-V"
  rect 1.6x1.6 / inner round 1.524 / far side rect 1.6x1.6 hole 1: 1(-3.75,0.5)
  round 1.6 / inner round 1.524 / far side round 1.6 hole 1: 2(-1.25,0.5) 3(1.25,0.5)
  round 1.6 hole 1: 4(3.75,0.5)
  silkscreen extent -6.25,-2.9 6.25,2.9, body extent -6.25,-2.9 6.25,2.9, height 3.81
ZH1P5MM_TH_2P [mm] "ZH1P5MM_TH_2P"
  round 1.05 / inner round 1.524 / far side round 1.05 hole 0.65: 1(-0.75,0.65)
  round 1.05 hole 0.65: 2(0.75,0.65)
  silkscreen extent -2.25,-1.85 2.25,1.85

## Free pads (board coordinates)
  round 40 smd: 1(73,3463.37) 1(275,341.37) 1(4583,3517.37) 1(4902,108.37) ""(73,3463.37) ""(275,341.37) ""(4583,3517.37) ""(4902,108.37)
  round 40 smd far side: 1(93,367.37) 1(351,3550.37) 1(4892,104.37) 1(5165,2810.37) ""(93,367.37) ""(351,3550.37) ""(4892,104.37) ""(5165,2810.37)
  round 40 / inner round 60 / far side round 40 all layers, no hole: ""(700,-177.16) ""(700,3956.68) ""(4236.21,3956.68) ""(4536.21,-177.16)

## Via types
v1: diameter 20, hole 10, TOP to BOTTOM, 1912 vias
v2: diameter 40/50/50/50/50/40 (per signal layer), hole 0, TOP to BOTTOM, 4 vias

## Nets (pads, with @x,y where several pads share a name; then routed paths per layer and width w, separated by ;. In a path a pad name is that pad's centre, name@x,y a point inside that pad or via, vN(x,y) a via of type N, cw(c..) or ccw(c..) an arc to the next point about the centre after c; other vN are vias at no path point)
1V05_AVDD_PHY: C83.1 C84.1 C85.1 C86.1 R107.2 U14.3 U14.8 U14.38 | length 853.4
  TOP w15: v1(4095,2604.37) 4149,2604.37 4160,2615.37 4319,2615.37 v1(4350,2584.37) v1(4430,2584.37)
  BOTTOM w8: 4260.63,2453.74 U14.38@4296.57,2453.74 ; v1(4350,2584.37) 4355,2579.37 4355,2569.37 4355.63,2568.74 U14.3@4355.63,2512.8 ; v1(4430,2584.37) 4434.37,2580 U14.8@4434.37,2512.8
  BOTTOM w10: C85.1@4195,2519.69 4225,2489.69 4225,2489.37 4260.63,2453.74
  BOTTOM w12: v1(4350,2584.37) C84.1@4350,2614.69 ; v1(4430,2584.37) 4435,2589.37 C83.1@4435,2614.69
  BOTTOM w15: v1(4095,2604.37) 4134.68,2564.69 C86.1@4134.68,2559.37 R107.2@4134.68,2519.37 4158.98,2519.37 4159.3,2519.69 C85.1@4195,2519.69
1V05_DVDD_PHY: C79.1 C80.1 C81.1 C82.1 R106.1 U14.21 | length 37.8
  BOTTOM w8: U14.21@4465.87,2315.94 4465.87,2282.22 v1(4468.72,2279.37)
1V05_PHY: C72.1 C73.1 L3.2 R106.2 R107.1 | length 599.3
  TOP w15: v1(4010,2304.37) 4033.5,2280.87 4105,2280.87 4120,2265.87 4120,2159.37 4135,2144.37 4195,2144.37
  BOTTOM w15: v1(4010,2304.37) 4015,2309.37 4015,2499.37 4035,2519.37 R107.1@4095.32,2519.37
  other v1: 4185,2089.37 4230,2089.37
3V3_DVDD_PHY: C70.1 C71.1 C87.1 C88.1 C89.1 R80.1 R81.1 R82.1 R93.1 R94.1 R95.1 R104.2 R105.1 R240.1 U14.11 U14.28 U14.29 U14.40 | length 1836.2
  TOP w10: v1(4155.32,2182.57) 4339.81,2182.57 4349.81,2192.57 v1(4349.81,2239.37) ; v1(4545,2584.37) 4568,2607.37 4735,2607.37 4755,2587.37 v1(4755,2469.37)
  TOP w15: v1(4285,2584.37) 4316.77,2584.37 4346.77,2554.37 4370,2554.37 4380,2544.37
  ART03 w10: v1(4349.81,2239.37) 4354.59,2234.59 v1(4620,2234.59)
  ART03 w12: v1(4455,2034.37) v1(4500,2034.37) 4532.8,2067.17 4587.8,2067.17 v1(4620,2099.37)
  BOTTOM w8: U14.11@4493.43,2485.24 4493.43,2502.8
  BOTTOM w10: v1(4455,2034.37) R80.1@4455,2064.69 ; 4493.43,2502.8 4493.43,2517.8 4505,2529.37 v1(4505,2584.37) ; v1(4500,2034.37) R81.1@4500,2064.69 ; R82.1@4590,2064.69 4620,2094.69 v1(4620,2099.37) v1(4620,2234.59) ; C87.1@4595.32,2614.37 4635,2574.69 R105.1@4635,2554.05 ; R94.1@4634.68,2429.37 R93.1@4634.68,2469.37 v1(4755,2469.37)
  BOTTOM w12: R95.1@4155.32,2154.37 v1(4155.32,2182.57) R104.2@4155.32,2209.37
  BOTTOM w15: v1(4505,2584.37) C89.1@4505,2614.69
  other v1: 4350,2279.37
3V3_IMAGE0: C133.1 C138.1 J19.4 J19.5 R147.1 R151.1 U26.1 | length 407.6
  BOTTOM w10: R151.1@4825.32,2694.37 R147.1@4825.32,2734.37 4795,2764.69 4795,2878.67 4802,2885.67 4802,2949.37 4812,2959.37 4935,2959.37
  other v1: 4995,3389.37 5030,3389.37
3V3_IMAGE1: C134.1 C135.1 J20.4 J20.5 R149.1 R153.1 U27.1 | length 275.1
  TOP w10: 4825,2424.37 4825.32,2424.69 v1(4825.32,2629.37)
  BOTTOM w10: R149.1@4825.32,2559.37 R153.1@4825.32,2599.37 v1(4825.32,2629.37)
3V3_WLAN: C95.1 C96.1 Q6.3 U15.8
  other v1: 3835,1594.37 3870,1594.37
5V0_CAM0/1: C140.1 C141.1 J21.1 J21.2 J21.3 J22.1 J22.2 J22.3 U28.1
  other v1: 5050,1884.37 5090,1884.37 5050,1924.37 5090,1924.37
5V0_CAM2/3: C143.1 C144.1 J23.1 J23.2 J23.3 J24.1 J24.2 J24.3 U29.1
  other v1: 5050,1018.23 5090,1018.23 5050,1058.23 5090,1058.23
5V0_IMAGE0: C129.1 C130.1 J19.1 J19.2 J19.3 U25.1
  other v1: 5007,3130 5007,3169.37
5V0_IMAGE1: C126.1 C127.1 J20.1 J20.2 J20.3 U24.1
B_DM1: J16.2 R116.1 U16.4 U16.7 | length 1138.1
  TOP w5.3: J16.2@3461.29,3400.86 3427.34,3400.86 3422.04,3406.16 3422.04,3455.02 3434.09,3467.07 3569.91,3467.07 3677.2,3359.77 3783.4,3359.77 3794,3349.17 3794,3274.37 v1(3784,3264.37)
  BOTTOM w5.3: R116.1@3520,2979.05 3531.89,2990.94 3531.89,3011.26 3523.38,3019.78 3523.38,3032.37 3519.68,3036.06 U16.7@3519.68,3057.15 U16.4@3519.68,3091.59 3519.68,3112.68 3523.38,3116.37 3523.38,3139.37 3553.38,3169.37 3760,3169.37 3792.7,3202.07 3792.7,3255.67 v1(3784,3264.37)
B_DM2: J16.11 R112.1 U16.1 U16.10 | length 407.2
  TOP w5.3: v1(3423.49,3142.52) 3423.87,3142.52 3437.57,3156.22 3454.85,3156.22 3464.49,3165.86 3464.49,3233.41 3451,3246.9 3451,3264.57 J16.11@3461.29,3274.86
  BOTTOM w5.3: v1(3423.49,3142.52) 3430.84,3149.87 3431.22,3149.87 3436.3,3154.95 3458.42,3154.95 3468.02,3145.35 3468.02,3120.07 3460.63,3112.68 U16.1@3460.63,3091.59 U16.10@3460.63,3057.15 3460.63,3039.74 3468.02,3032.35 3468.02,3007.07 R112.1@3440,2979.05
B_DM3: J17.2 R114.1 U18.2 U18.9 | length 1435.8
  BOTTOM w5.3: R114.1@3729.68,2249.37 3746.89,2232.16 3772.79,2232.16 3780.32,2239.69 U18.2@3797.78,2239.69 U18.9@3832.22,2239.69 3853.31,2239.69 3860.7,2232.3 3881.01,2232.3 3908.65,2259.95 3908.65,2426.1 3890,2444.75 3890,2735.17 3790,2835.17 3790,3136.77 3911.3,3258.07 4010.44,3258.07 4015.74,3263.37 J17.2@4015.74,3291.33
B_DP1: J16.3 R117.1 U16.5 U16.6 | length 1164.3
  TOP w5.3: J16.3@3382.49,3400.86 3404.44,3400.86 3409.74,3406.16 3409.74,3460.11 3429,3479.37 3575,3479.37 3682.3,3372.07 3788.49,3372.07 3806.3,3354.26 3806.3,3268.07 v1(3810,3264.37)
  BOTTOM w5.3: R117.1@3560,2979.05 3545,2994.05 3545,3015.55 3535.68,3024.87 3535.68,3032.37 3539.37,3036.06 U16.6@3539.37,3057.15 U16.5@3539.37,3091.59 3539.37,3112.68 3535.68,3116.37 3535.68,3134.28 3558.47,3157.07 3765.09,3157.07 3805,3196.97 3805,3259.37 v1(3810,3264.37)
B_DP2: J16.12 R113.1 U16.2 U16.9 | length 410.2
  TOP w5.3: J16.12@3382.49,3274.86 3405.65,3274.86 3452.2,3228.31 3452.2,3173.82 3446.89,3168.52 v1(3423.49,3168.52)
  BOTTOM w5.3: v1(3423.49,3168.52) 3424.76,3167.25 3463.51,3167.25 3480.32,3150.45 U16.2@3480.32,3091.59 U16.9@3480.32,3057.15 3480.32,2979.37 R113.1@3480,2979.05
B_DP3: J17.3 R115.1 U18.1 U18.10 | length 1426.9
  BOTTOM w5.3: R115.1@3729.68,2209.37 3740.17,2219.86 3777.89,2219.86 3778.03,2220 U18.1@3797.78,2220 U18.10@3832.22,2220 3886.1,2220 3920.95,2254.85 3920.95,2431.19 3902.3,2449.84 3902.3,2740.27 3802.3,2840.27 3802.3,3131.67 3916.4,3245.77 4010.44,3245.77 4015.74,3240.47 J17.3@4015.74,3212.51
BAT_RTC: C50.1 D5.1 D6.2 J8.1 | length 251.7
  BOTTOM w15: D5.1@448.5,3111.87 448.5,3095.87 489.68,3054.69 C50.1@495,3054.69 D6.2@540,3054.69 632.76,3054.69 J8.1@657.04,3078.97
BD_CH3: C38.1 J4.48 R23.2 R24.1 | length 203.4
  TOP w6: v1(1290,2754.37) 1295.76,2748.61 J4.48@1295.76,2677.37
  BOTTOM w6: v1(1290,2754.37) 1310,2774.37 C38.1@1325.32,2774.37 R24.1@1325.32,2734.37 1325.32,2694.37 R23.2@1325,2694.05
CAM0/1_PWR_EN: J5.69 R165.1 | length 4343.7
  TOP w6: v1(2366.26,1003.74) 2440.63,1003.74 2453,991.37 2453,896.37 2475.59,873.78 J5.69@2475.59,826.59
  ART03 w5.5: v1(2366.26,1003.74) 2451.89,1089.37 4018,1089.37 4030,1101.37 4030,1494.37 4050,1514.37 4530,1514.37 4690,1354.37 4789.6,1354.37 4814.6,1379.37 5050,1379.37 5109,1438.37 5109,1892.37 5096,1905.37 5076,1905.37 5070,1911.37 5070,2008.37 5054,2024.37 4973.6,2024.37 4965,2032.97 v1(4965,2069.37)
  BOTTOM w6: v1(4965,2069.37) 4965,2069.69 R165.1@4995,2099.69
CAM0_NRST: J4.6 J21.22 | length 6886.2
  TOP w6: v1(741,2449.37) 721,2469.37 721,2582.37 733,2594.37 923,2594.37 965.05,2636.42 J4.6@965.05,2677.37
  ART03 w5.5: v1(741,2449.37) 720,2449.37 576,2305.37 576,1317.37 587,1306.37 2137,1306.37 2157,1326.37 2306,1326.37 2328,1304.37 3939,1304.37 3955,1320.37 3955,1531.57 3985.3,1561.87 4550.38,1561.87 4551.48,1560.77 4553.6,1560.77 v1(4710,1404.37)
  BOTTOM w6: v1(4710,1404.37) 4665.9,1448.47 4665.9,1770.27 4813,1917.37 4912,1917.37 4949.45,1879.92 J21.22@4978.61,1879.92
CAM0_PWDN: J4.4 J21.15 | length 7030
  TOP w6: v1(701.63,2488.74) 702,2489.11 702,2612.37 729,2639.37 937.3,2639.37 949.3,2651.37 J4.4@949.3,2677.37
  ART03 w5.5: v1(701.63,2488.74) 696.37,2488.74 541,2333.37 541,1273.37 560,1254.37 2187,1254.37 2202,1239.37 2303,1239.37 2318,1254.37 3993,1254.37 4005,1266.37 4005,1509.37 4025,1529.37 4535,1529.37 4695,1369.37 4770.2,1369.37 4800.2,1399.37 4875,1399.37 4895.2,1419.57 5050.4,1419.57 5075,1444.17 v1(5075,1529.37)
  BOTTOM w6: J21.15@4978.61,1742.12 5090.25,1742.12 5100,1732.37 5100,1554.37 v1(5075,1529.37)
CAM1_NRST: J4.12 J22.22 | length 6392.7
  TOP w6: v1(945,2716.08) 1003.29,2716.08 1012.29,2707.08 J4.12@1012.29,2677.37 ; v1(4920,1494.37) 4931.53,1505.9 J22.22@4978.61,1505.9
  ART03 w5.5: v1(945,2716.08) 945,2658.37 797,2510.37 797,2442.37 784,2429.37 728,2429.37 596,2297.37 596,1339.37 606,1329.37 2123,1329.37 2139,1345.37 2317,1345.37 2333,1329.37 3914,1329.37 3930,1345.37 3930,1554.37 3955,1579.37 4560,1579.37 4715,1424.37 4873.8,1424.37 4920,1470.57 v1(4920,1494.37)
CAM1_PWDN: J4.8 J22.15 | length 6722.2
  TOP w6: v1(741,2488.74) 741,2560.37 755,2574.37 930,2574.37 980.79,2625.16 J4.8@980.79,2677.37 ; v1(4755,1404.37) 4704,1455.37 4704,1628.37 4719.33,1643.7 J22.15@4978.61,1643.7
  ART03 w5.5: v1(741,2488.74) 719.13,2466.87 702.75,2466.87 558.5,2322.62 558.5,1287.87 564,1282.37 3974.5,1282.37 3980,1287.87 3980,1524.37 4000,1544.37 4543.13,1544.37 4702.13,1385.37 4736,1385.37 v1(4755,1404.37)
CAM2/3_PWR_EN: J5.71 R167.1 | length 2893.7
  TOP w6: J5.71@2491.34,826.59 2491.34,893.03 2475,909.37 2475,943.74 v1(2494,962.74)
  ART03 w5.5: v1(2494,962.74) 2560.63,1029.37 4080,1029.37 4100,1009.37 4100,939.37 4114,925.37 4486,925.37 4800.32,1239.69 v1(4865,1239.69)
  BOTTOM w6: v1(4865,1239.69) R167.1@4995,1239.69
CAM2_NRST: J4.16 J23.22 | length 8303.5
  TOP w6: v1(866.26,2755.45) 1013.92,2755.45 1043.79,2725.58 J4.16@1043.79,2677.37
  ART03 w5.5: v1(866.26,2755.45) 887,2734.71 887,2706.37 734,2553.37 675,2553.37 447.5,2325.87 447.5,1006.87 345,904.37 345,699.37 360,684.37 360,509.37 432.68,436.69 1227.68,436.69 1326.21,338.16 2466.4,338.16 2492.59,311.97 2601.6,311.97 2627.79,338.16 2936.21,338.16 2955,319.37 3195,319.37 3205,329.37 4145,329.37 4230,414.37 4845,414.37 4855,424.37 4855,474.37 4880,499.37 5030,499.37 5105,574.37 5105,829.37 v1(5125,849.37)
  BOTTOM w8: J23.22@4978.61,1013.78 5015.59,1013.78 5045,984.37 5105,984.37 5114,975.37 5114,860.37 v1(5125,849.37)
CAM2_PWDN: J4.14 J23.15 | length 8160.9
  TOP w6: v1(866.26,2716.08) 885.55,2735.37 1009,2735.37 1028.04,2716.33 J4.14@1028.04,2677.37
  ART03 w5.5: v1(866.26,2716.08) 723.55,2573.37 666.87,2573.37 425,2331.5 425,1019.37 325,919.37 325,689.37 340,674.37 340,493.74 430.37,403.37 1231.91,403.37 1320.91,314.37 2455,314.37 2476.8,292.57 2613,292.57 2634.8,314.37 2925,314.37 2946,293.37 3264,293.37 3275,304.37 4155,304.37 4230,379.37 4570,379.37 4585,394.37 4880,394.37 4891,405.37 4891,465.37 4905,479.37 5045,479.37 5125,559.37 v1(5125,729.37)
  BOTTOM w6: J23.15@4978.61,875.98 5011.52,875.98 5017.13,870.37 5069,870.37 5080,859.37 5080,774.37 v1(5125,729.37)
CAM3_NRST: J4.22 J24.22 | length 7580.1
  TOP w6: v1(945,2794.82) 1069.55,2794.82 1091.03,2773.34 J4.22@1091.03,2677.37
  TOP w8: v1(4475,439.37) 4500,464.37 4740,464.37 4870,594.37 4870,629.37 4880.39,639.76 J24.22@4978.61,639.76
  ART03 w5.5: v1(945,2794.82) 923.35,2773.16 923.35,2662.72 774,2513.37 695,2513.37 500,2318.37 500,1209.12 482.5,1191.62 482.5,971.87 385,874.37 385,719.37 400,704.37 400,554.37 463,491.37 547.04,491.37 559.04,479.37 1240,479.37 1340,379.37 3025,379.37 3035,369.37 4131.87,369.37 4221.87,459.37 4455,459.37 v1(4475,439.37)
CAM3_PWDN: J4.20 J24.15 | length 7722.5
  TOP w6: v1(905.63,2794.82) 928.08,2772.37 1062,2772.37 1075.28,2759.09 J4.20@1075.28,2677.37 ; v1(4435,439.37) 4480,484.37 4730,484.37 4845,599.37 4845,729.37 4893.19,777.56 J24.15@4978.61,777.56
  ART03 w5.5: v1(905.63,2794.82) 905.85,2794.61 905.85,2701.22 904.5,2699.87 904.5,2699.12 741.25,2535.87 740.5,2535.87 738,2533.37 685,2533.37 482.5,2330.87 482.5,1216.37 465,1198.87 465,989.37 365,889.37 365,709.37 380,694.37 380,539.37 461,458.37 1236,458.37 1335,359.37 2950,359.37 2970,339.37 3185,339.37 3195,349.37 4140,349.37 4230,439.37 v1(4435,439.37)
CAN1_H: D24.2 R74.1 R78.1 U12.7 | length 1004.9
  BOTTOM w12: R74.1@2780,540.87 2780,569.37 2800,589.37 2800,789.37 2865,854.37 2865,973.82 D24.2@2795,1043.82 2865,1113.82 2865,1322.87 R78.1@2843.5,1344.37 2850,1350.87 U12.7@2850,1440.94
CAN1_L: D25.2 R75.1 R78.2 U12.6 | length 1004.5
  BOTTOM w12: R75.1@2835,540.87 2835,569.37 2818,586.37 2818,779.09 2885,846.09 2885,973.82 D25.2@2955,1043.82 2885,1113.82 2885,1322.87 R78.2@2906.5,1344.37 2900,1350.87 U12.6@2900,1440.94
CAN1_RX_M1: J4.30 U12.4 | length 3912.3
  TOP w6: v1(1017.37,2582.37) 1051,2582.37 1096.2,2627.57 1131.4,2627.57 1154.02,2650.19 J4.30@1154.02,2677.37
  ART03 w5.5: v1(1017.37,2582.37) 998.37,2563.37 931,2563.37 876,2508.37 876,2423.37 842,2389.37 741,2389.37 634,2282.37 634,1635.37 651,1618.37 866,1618.37 953,1531.37 2477,1531.37 2528,1582.37 2711,1582.37 2720,1591.37 v1(2720,1649.37)
  BOTTOM w6: v1(2720,1649.37) 2720,1669.37 2740,1689.37 2940,1689.37 2950,1679.37 U12.4@2950,1637.8
CAN1_TX_M1: J4.28 U12.1 | length 3766.9
  TOP w6: v1(978,2582.37) 990.5,2582.37 1013.5,2605.37 1043,2605.37 1082.4,2644.77 1126.28,2644.77 1138.28,2656.77 J4.28@1138.28,2677.37
  ART03 w5.5: v1(978,2582.37) 977.5,2581.87 897.5,2581.87 854,2538.37 854,2448.37 836,2430.37 810,2430.37 789,2409.37 733,2409.37 615,2291.37 615,1624.37 640,1599.37 855,1599.37 940,1514.37 2549,1514.37 2573,1538.37 2741,1538.37 2755,1552.37 v1(2755,1649.37)
  BOTTOM w6: v1(2755,1649.37) 2795,1649.37 2800,1644.37 U12.1@2800,1637.8
CAN2_H: D26.2 R76.1 R79.1 U13.7 | length 975.9
  BOTTOM w12: R76.1@2530,540.87 2530,569.37 2545,584.37 2545,973.82 D26.2@2475,1043.82 2545,1113.82 2545,1322.87 R79.1@2523.5,1344.37 2530,1350.87 U13.7@2530,1440.94
CAN2_L: D27.2 R77.1 R79.2 U13.6 | length 981.7
  BOTTOM w12: U13.6@2580,1440.94 2580,1350.87 R79.2@2586.5,1344.37 2567.88,1325.75 2567.88,1110.94 D27.2@2635,1043.82 2624.45,1043.82 2565,984.37 2565,584.37 2585,564.37 R77.1@2585,540.87
CAN2_RX_M0: J4.36 U13.4 | length 3424.1
  TOP w6: v1(1145,2585) 1177.63,2585 1201.27,2608.64 J4.36@1201.27,2677.37
  ART03 w5.5: v1(1145,2585) 1121.37,2561.37 1068.94,2561.37 856.94,2349.37 753,2349.37 679,2275.37 679,1764.31 699.94,1743.37 1201,1743.37 1280,1664.37 1731.06,1664.37 1756.06,1689.37 2440,1689.37 2480,1649.37 v1(2670,1649.37)
  BOTTOM w6: U13.4@2630,1637.8 2630,1683.37 2636,1689.37 2664.24,1689.37 2670,1683.61 v1(2670,1649.37)
CAN2_TX_M0: J4.34 U13.1 | length 3183.9
  TOP w6: v1(1105.63,2585) 1124.63,2604 1167.63,2604 1185.52,2621.89 J4.34@1185.52,2677.37
  ART03 w5.5: v1(1105.63,2585) 1066.63,2585 851,2369.37 746,2369.37 655,2278.37 655,1754.37 690,1719.37 1195,1719.37 1270,1644.37 1745,1644.37 1770,1669.37 v1(2420,1669.37)
  BOTTOM w6: v1(2420,1669.37) 2436,1685.37 2474,1685.37 2480,1679.37 U13.1@2480,1637.8
CTP0_INT: J6.44 J19.11 R147.2 | length 3452.7
  TOP w6: J6.44@2270.86,2677.37 2270.86,2851.03 v1(2309.2,2889.37) ; v1(4878,2980.37) 4878,2992.35 4886.02,3000.37 4925,3000.37 4937,2988.37 4937,2728.16 v1(4935,2726.16)
  ART03 w5.5: v1(2309.2,2889.37) 2329.57,2909.74 2329.57,2995.93 2404,3070.37 2765,3070.37 2802,3033.37 4163,3033.37 4220,2976.37 4470.8,2976.37 4493,2954.17 4557.8,2954.17 4573,2969.37 4730,2969.37 4742,2957.37 4855,2957.37 v1(4878,2980.37)
  BOTTOM w6: R147.2@4864.68,2734.37 4890,2734.37 4898.21,2726.16 v1(4935,2726.16) J19.11@4980.62,2726.16
CTP0_RST: J5.62 J19.12 R151.2 | length 5603.3
  TOP w6: J5.62@2412.6,722.26 2412.6,496.77 v1(2420,489.37)
  ART03 w5.5: v1(2420,489.37) 3060,489.37 3100,449.37 4090,449.37 4180,539.37 4994.64,539.37 5070,614.73 5070,854.37 5125,909.37 5125,1194.37 5149.5,1218.87 5149.5,1919.62 5146,1923.12 5146,1928.37 5120,1954.37 5120,1981.37 5128,1989.37 5162,1989.37 5170,1997.37 5170,2056.37 5162,2064.37 5045,2064.37 v1(5025,2044.37)
  BOTTOM w6: J19.12@4980.62,2706.47 4902.1,2706.47 4890,2694.37 R151.2@4864.68,2694.37 4864.68,2639.69 4880,2624.37 4910,2624.37 4942,2592.37 4942,2419.37 4925,2402.37 4925,2044.37 4950,2019.37 5000,2019.37 v1(5025,2044.37)
CTP1_INT: J6.46 J20.11 R149.2 | length 3390.4
  TOP w6: J6.46@2286.61,2677.37 2286.61,2832.1 2328.88,2874.37 2328.88,2909.68 v1(2348.57,2929.37) ; v1(4680,2949.37) 4715,2914.37 4734,2914.37 4740,2908.37 4740,2749.37 4760,2729.37 4815,2729.37 4835,2709.37 4835,2669.37 4860,2644.37 4860,2594.37 v1(4895,2559.37) 4905.36,2549.01 J20.11@4980.62,2549.01
  ART03 w5.5: v1(2348.57,2929.37) 2348.57,2987.93 2412,3051.37 2755,3051.37 2792,3014.37 4144.2,3014.37 4223.2,2935.37 4573,2935.37 4587,2949.37 v1(4680,2949.37)
  BOTTOM w6: R149.2@4864.68,2559.37 v1(4895,2559.37)
CTP1_RST: J6.70 J20.12 R153.2 | length 3067.3
  TOP w6: J6.70@2475.58,2677.37 2475.58,2740.58 2570,2835 v1(2570,2890.01) ; v1(4781,2894.37) 4760,2873.37 4760,2759.37 4770,2749.37 4825,2749.37 4856.4,2717.97 4856.4,2681.66 4878,2660.07 4878,2616.37 v1(4895,2599.37) 4925.67,2568.7 J20.12@4980.62,2568.7
  ART03 w5.5: v1(2570,2890.01) 2590.36,2910.37 2649,2910.37 2704,2855.37 3524,2855.37 3548,2879.37 3795.8,2879.37 3840.1,2835.07 4625.45,2835.07 4661.75,2871.37 4758,2871.37 v1(4781,2894.37)
  BOTTOM w6: R153.2@4864.68,2599.37 v1(4895,2599.37)
DBG_RX: R27.2 U6.2 | length 168.2
  BOTTOM w6: U6.2@1130.43,394.69 1184,394.69 1190,388.69 1190,320.37 1184,314.37 R27.2@1154.68,314.37
DBG_RXD: J7.3 R27.1 Z4.1 | length 194.6
  BOTTOM w6: J7.3@1033.46,177.48 1033.46,232.83 1074.68,274.05 Z4.1@1074.68,314.37 R27.1@1115.32,314.37
DBG_TX: R26.2 U5.4 | length 64.8
  BOTTOM w6: R26.2@815.32,314.37 815.32,329.69 839.57,353.94 U5.4@839.57,369.09
DBG_TXD: J7.2 R26.1 Z3.1 | length 194
  BOTTOM w6: R26.1@854.68,314.37 Z3.1@895.32,314.37 895.32,259.05 935.04,219.33 J7.2@935.04,177.48
DEBUG_RX: J5.78 R29.2 U6.4 | length 1947.2
  TOP w6: v1(1015,369.09) 1034.72,349.37 2480,349.37 2538.58,407.95 J5.78@2538.58,722.26
  BOTTOM w6: R29.2@985,374.69 990.6,369.09 v1(1015,369.09) U6.4@1059.57,369.09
